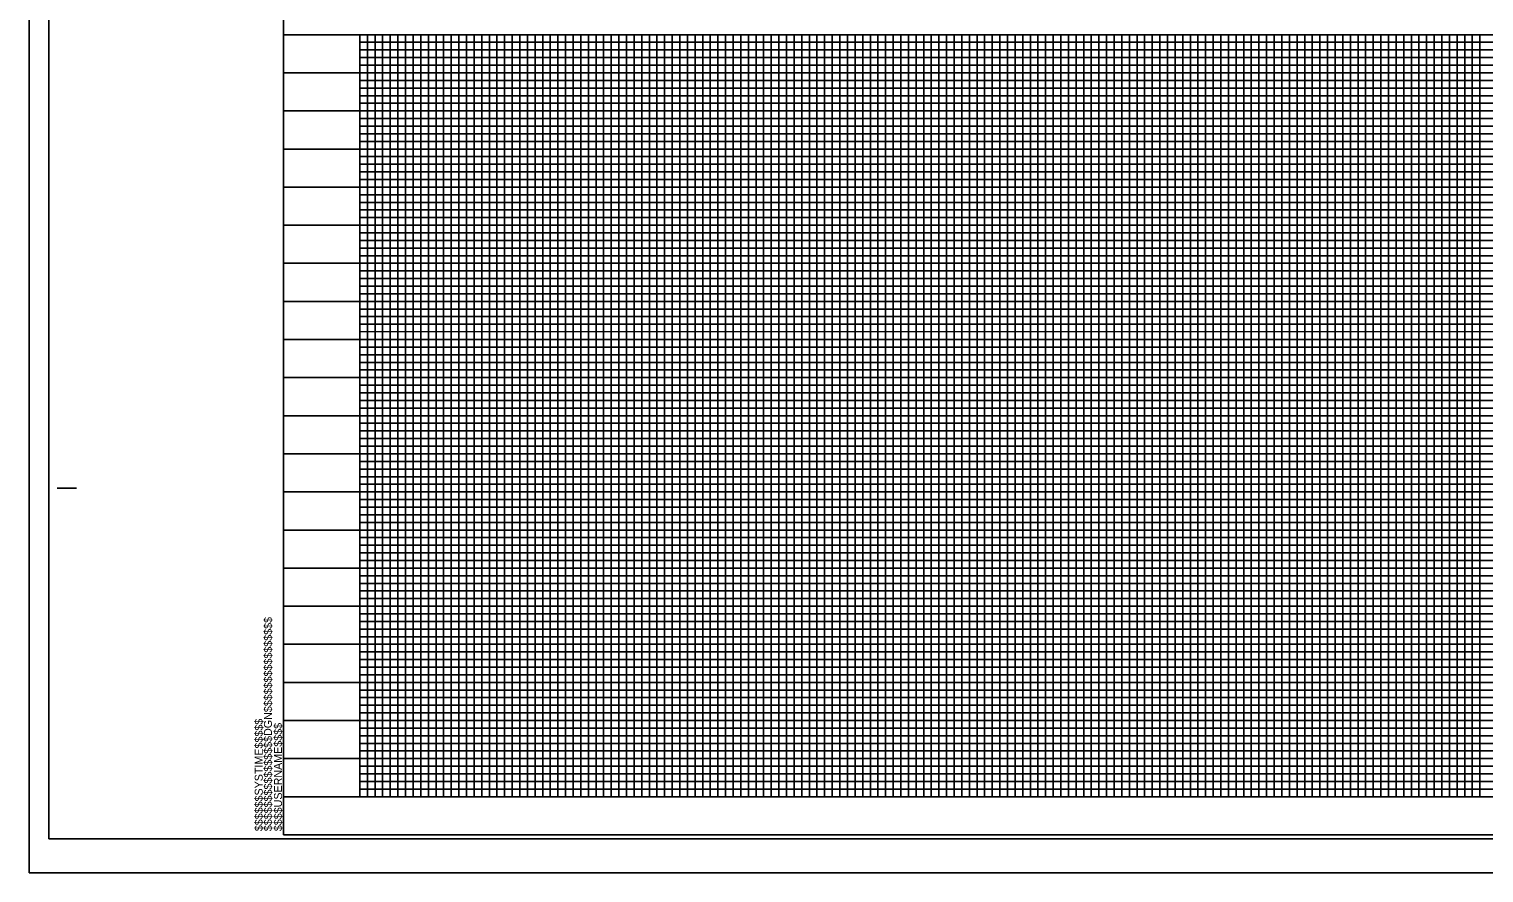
# Model space of a CAD drawing. Extents: x 1754992 to 1757273, y 732111 to 735411.
# Drawn here: x 1755181 to 1756135, y 732111 to 732664 of the extents above; entities that cross this region are included whole.
import ezdxf

# ---------------------------------------------------------------- set-up
doc = ezdxf.new("R2010")
doc.units = 0
for name, color, linetype in [('Scratch_Level_3', 7, 'Continuous'), ('Sheet Cutting Line CELL', 7, 'Continuous'), ('Sheet DOT Grid CELL', 7, 'Continuous'), ('Sheet Plot Border Inside CELL', 7, 'Continuous'), ('Sheet Plot Border Outside CELL', 7, 'Continuous'), ('Sheet Profile CELL', 7, 'Continuous'), ('Sheet Profile Grid Major CELL', 7, 'Continuous'), ('Sheet Profile Grid Middle CELL', 7, 'Continuous'), ('Sheet Profile Grid Minor CELL', 7, 'Continuous')]:
    doc.layers.add(name, color=color, linetype=linetype)

msp = doc.modelspace()

# ---------------------------------------------------------------- linework, layer by layer
at = {"layer": 'Scratch_Level_3'}
msp.add_lwpolyline([(1755397.67, 732660.78), (1756797.67, 732660.78), (1756797.67, 732160.78), (1755397.67, 732160.78)], close=True, dxfattribs=at)
at = {"layer": 'Sheet Cutting Line CELL'}
for p, q in [((1755180.67, 733210.78), (1755180.67, 732110.78)), ((1755180.67, 732110.78), (1756864.67, 732110.78))]:
    msp.add_line(p, q, dxfattribs=at)
at = {"layer": 'Sheet DOT Grid CELL'}
for p, q in [((1755347.67, 732660.78), (1756847.56, 732660.78)), ((1755397.67, 732660.78), (1755397.67, 732160.78)), ((1755447.67, 732660.78), (1755447.67, 732160.78)), ((1755497.67, 732660.78), (1755497.67, 732160.78)), ((1755547.67, 732660.78), (1755547.67, 732160.78)), ((1755597.67, 732660.78), (1755597.67, 732160.78)), ((1755647.67, 732660.78), (1755647.67, 732160.78)), ((1755697.67, 732660.78), (1755697.67, 732160.78)), ((1755747.67, 732660.78), (1755747.67, 732160.78)), ((1755797.67, 732660.78), (1755797.67, 732160.78)), ((1755847.67, 732660.78), (1755847.67, 732160.78)), ((1755897.67, 732660.78), (1755897.67, 732160.78)), ((1755947.67, 732660.78), (1755947.67, 732160.78)), ((1755997.67, 732660.78), (1755997.67, 732160.78)), ((1756047.67, 732660.78), (1756047.67, 732160.78)), ((1756097.67, 732660.78), (1756097.67, 732160.78)), ((1755347.67, 732610.78), (1756847.56, 732610.78)), ((1755347.67, 732560.78), (1756847.56, 732560.78)), ((1755347.67, 732510.78), (1756847.56, 732510.78)), ((1755347.67, 732460.78), (1756847.56, 732460.78)), ((1755347.67, 732410.78), (1756847.56, 732410.78)), ((1755347.67, 732360.78), (1756847.56, 732360.78)), ((1755347.67, 732310.78), (1756847.56, 732310.78)), ((1755347.67, 732260.78), (1756847.56, 732260.78)), ((1755347.67, 732210.78), (1756847.56, 732210.78))]:
    msp.add_line(p, q, dxfattribs=at)
at = {"layer": 'Sheet Plot Border Inside CELL'}
msp.add_lwpolyline([(1755193.67, 732133.23), (1756860.17, 732133.23), (1756860.17, 733188.33), (1755193.67, 733188.33)], close=True, dxfattribs=at)
at = {"layer": 'Sheet Plot Border Outside CELL'}
msp.add_lwpolyline([(1755180.67, 732110.78), (1756864.67, 732110.78), (1756864.67, 733210.78), (1755180.67, 733210.78)], close=True, dxfattribs=at)
at = {"layer": 'Sheet Profile CELL'}
for p, q in [((1755347.67, 732660.78), (1756847.67, 732660.78)), ((1755199.17, 732363.28), (1755211.67, 732363.28)), ((1756847.67, 732160.78), (1755347.67, 732160.78)), ((1755347.67, 732135.78), (1756847.67, 732135.78)), ((1755347.67, 732135.78), (1755347.67, 732135.78)), ((1755347.67, 732135.78), (1755347.67, 732135.78)), ((1755347.67, 732135.78), (1755347.67, 732135.78)), ((1755347.67, 732135.78), (1755347.67, 732135.78)), ((1755347.67, 732135.78), (1755347.67, 732135.78)), ((1755347.67, 732135.78), (1755347.67, 732135.78)), ((1755347.67, 732135.78), (1755347.67, 732135.78))]:
    msp.add_line(p, q, dxfattribs=at)
msp.add_lwpolyline([(1756847.67, 733185.78), (1755347.67, 733185.78), (1755347.67, 732135.78), (1756847.67, 732135.78)], close=True, dxfattribs=at)
msp.add_lwpolyline([(1755385.17, 732135.78), (1755385.17, 732135.78)], dxfattribs=at)
at = {"layer": 'Sheet Profile Grid Major CELL'}
for p, q in [((1755847.67, 732660.78), (1755897.67, 732660.78)), ((1755947.67, 732660.78), (1755997.67, 732660.78)), ((1756047.67, 732660.78), (1756097.67, 732660.78)), ((1755347.67, 732160.78), (1755347.67, 732160.78))]:
    msp.add_line(p, q, dxfattribs=at)
for points in [[(1755397.67, 732660.78), (1755397.67, 732160.78), (1755447.67, 732160.78), (1755447.67, 732660.78), (1755497.67, 732660.78), (1755497.67, 732160.78), (1755547.67, 732160.78), (1755547.67, 732660.78), (1755597.67, 732660.78), (1755597.67, 732160.78), (1755647.67, 732160.78), (1755647.67, 732660.78), (1755697.67, 732660.78), (1755697.67, 732160.78), (1755747.67, 732160.78), (1755747.67, 732660.78), (1755797.67, 732660.78), (1755797.67, 732160.78), (1755847.67, 732160.78), (1755847.67, 732660.78), (1755897.67, 732660.78), (1755897.67, 732160.78), (1755947.67, 732160.78), (1755947.67, 732660.78), (1755997.67, 732660.78), (1755997.67, 732160.78), (1756047.67, 732160.78), (1756047.67, 732660.78), (1756097.67, 732660.78), (1756097.67, 732160.78), (1756147.67, 732160.78)], [(1756847.67, 732610.78), (1755347.67, 732610.78)], [(1756847.67, 732560.78), (1755347.67, 732560.78), (1755347.67, 732510.78), (1756847.67, 732510.78)], [(1756847.67, 732460.78), (1755347.67, 732460.78), (1755347.67, 732410.78), (1756847.67, 732410.78)], [(1756847.67, 732360.78), (1755347.67, 732360.78), (1755347.67, 732310.78), (1756847.67, 732310.78)], [(1756847.67, 732260.78), (1755347.67, 732260.78), (1755347.67, 732260.78), (1755347.67, 732210.78), (1756847.67, 732210.78)], [(1756847.67, 732160.78), (1755347.67, 732160.78)]]:
    msp.add_lwpolyline(points, dxfattribs=at)
at = {"layer": 'Sheet Profile Grid Middle CELL'}
for points in [[(1755372.67, 732660.78), (1755422.67, 732660.78), (1755422.67, 732160.78), (1755472.67, 732160.78), (1755472.67, 732660.78), (1755522.67, 732660.78), (1755522.67, 732160.78), (1755572.67, 732160.78), (1755572.67, 732660.78), (1755622.67, 732660.78), (1755622.67, 732160.78), (1755672.67, 732160.78), (1755672.67, 732660.78), (1755722.67, 732660.78), (1755722.67, 732160.78), (1755772.67, 732160.78), (1755772.67, 732660.78), (1755822.67, 732660.78), (1755822.67, 732160.78), (1755872.67, 732160.78), (1755872.67, 732660.78), (1755922.67, 732660.78), (1755922.67, 732160.78), (1755972.67, 732160.78), (1755972.67, 732160.78), (1755972.67, 732660.78), (1756022.67, 732660.78), (1756022.67, 732160.78), (1756072.67, 732160.78), (1756072.67, 732660.78), (1756122.67, 732660.78), (1756122.67, 732160.78), (1756172.67, 732160.78)], [(1755347.67, 732635.78), (1756847.67, 732635.78)], [(1756847.67, 732585.78), (1755347.67, 732585.78), (1755347.67, 732535.78), (1756847.67, 732535.78)], [(1756847.67, 732485.78), (1755347.67, 732485.78), (1755347.67, 732435.78), (1756847.67, 732435.78)], [(1756847.67, 732385.78), (1755347.67, 732385.78), (1755347.67, 732335.78), (1756847.67, 732335.78)], [(1756847.67, 732285.78), (1755347.67, 732285.78), (1755347.67, 732235.78), (1756847.67, 732235.78)], [(1756847.67, 732185.78), (1755347.67, 732185.78)]]:
    msp.add_lwpolyline(points, dxfattribs=at)
at = {"layer": 'Sheet Profile Grid Minor CELL'}
for p, q in [((1755397.67, 732655.78), (1756797.67, 732655.78)), ((1756797.67, 732650.78), (1755397.67, 732650.78)), ((1755397.67, 732645.78), (1756797.67, 732645.78)), ((1756797.67, 732640.78), (1755397.67, 732640.78)), ((1755397.67, 732630.78), (1756797.67, 732630.78)), ((1756797.67, 732625.78), (1755397.67, 732625.78)), ((1755397.67, 732620.78), (1756797.67, 732620.78)), ((1756797.67, 732615.78), (1755397.67, 732615.78)), ((1755397.67, 732605.78), (1756797.67, 732605.78)), ((1756797.67, 732600.78), (1755397.67, 732600.78)), ((1755397.67, 732595.78), (1756797.67, 732595.78)), ((1756797.67, 732590.78), (1755397.67, 732590.78)), ((1755397.67, 732580.78), (1756797.67, 732580.78)), ((1756797.67, 732575.78), (1755397.67, 732575.78)), ((1755397.67, 732570.78), (1756797.67, 732570.78)), ((1756797.67, 732565.78), (1755397.67, 732565.78)), ((1755397.67, 732555.78), (1756797.67, 732555.78)), ((1756797.67, 732550.78), (1755397.67, 732550.78)), ((1755397.67, 732545.78), (1756797.67, 732545.78)), ((1756797.67, 732540.78), (1755397.67, 732540.78)), ((1755397.67, 732530.78), (1756797.67, 732530.78)), ((1756797.67, 732525.78), (1755397.67, 732525.78)), ((1755397.67, 732520.78), (1756797.67, 732520.78)), ((1756797.67, 732515.78), (1755397.67, 732515.78)), ((1755397.67, 732505.78), (1756797.67, 732505.78)), ((1756797.67, 732500.78), (1755397.67, 732500.78)), ((1755397.67, 732495.78), (1756797.67, 732495.78)), ((1756797.67, 732490.78), (1755397.67, 732490.78)), ((1755397.67, 732480.78), (1756797.67, 732480.78)), ((1756797.67, 732475.78), (1755397.67, 732475.78)), ((1755397.67, 732470.78), (1756797.67, 732470.78)), ((1756797.67, 732465.78), (1755397.67, 732465.93)), ((1755397.67, 732455.78), (1756797.67, 732455.78)), ((1756797.67, 732450.78), (1755397.67, 732450.78)), ((1755397.67, 732445.78), (1756797.67, 732445.78)), ((1756797.67, 732440.78), (1755397.67, 732440.78)), ((1755397.67, 732430.78), (1756797.67, 732430.78)), ((1756797.67, 732425.78), (1755397.67, 732425.78)), ((1755397.67, 732420.78), (1756797.67, 732420.78)), ((1756797.67, 732415.78), (1755397.67, 732415.78)), ((1755397.67, 732405.78), (1756797.67, 732405.78)), ((1756797.67, 732400.78), (1755397.67, 732400.78)), ((1755397.67, 732395.78), (1756797.67, 732395.78)), ((1756797.67, 732390.78), (1755397.67, 732390.78)), ((1755397.67, 732380.78), (1756797.67, 732380.78)), ((1756797.67, 732375.78), (1755397.67, 732375.78)), ((1755397.67, 732370.78), (1756797.67, 732370.78)), ((1756797.67, 732365.78), (1755397.67, 732365.78)), ((1755397.67, 732355.78), (1756797.67, 732355.78)), ((1756797.67, 732350.78), (1755397.67, 732350.78)), ((1755397.67, 732345.78), (1756797.67, 732345.78)), ((1756797.67, 732340.78), (1755397.67, 732340.78)), ((1755397.67, 732330.78), (1756797.67, 732330.78)), ((1756797.67, 732325.78), (1755397.67, 732325.78)), ((1755397.67, 732320.78), (1756797.67, 732320.78)), ((1756797.67, 732315.78), (1755397.67, 732315.78)), ((1755397.67, 732305.78), (1756797.67, 732305.78)), ((1756797.67, 732300.78), (1755397.67, 732300.78)), ((1755397.67, 732295.78), (1756797.67, 732295.78)), ((1756797.67, 732290.78), (1755397.67, 732290.78)), ((1755397.67, 732280.78), (1756797.67, 732280.78)), ((1756797.67, 732275.78), (1755397.67, 732275.78)), ((1755397.67, 732270.78), (1756797.67, 732270.78)), ((1756797.67, 732265.78), (1755397.67, 732265.78)), ((1755397.67, 732255.78), (1756797.67, 732255.78)), ((1756797.67, 732250.78), (1755397.67, 732250.78)), ((1755397.67, 732245.78), (1756797.67, 732245.78)), ((1756797.67, 732240.78), (1755397.67, 732240.78)), ((1755397.67, 732230.78), (1756797.67, 732230.78)), ((1756797.67, 732225.78), (1755397.67, 732225.78)), ((1755397.67, 732220.78), (1756797.67, 732220.78)), ((1756797.67, 732215.78), (1755397.67, 732215.78)), ((1755397.67, 732205.78), (1756797.67, 732205.78)), ((1756797.67, 732200.78), (1755397.67, 732200.78)), ((1755397.67, 732195.78), (1756797.67, 732195.78)), ((1756797.67, 732190.78), (1755397.67, 732190.78)), ((1755397.67, 732180.78), (1756797.67, 732180.78)), ((1756797.67, 732175.78), (1755397.67, 732175.78)), ((1755397.67, 732170.78), (1756797.67, 732170.78)), ((1755397.67, 732165.78), (1756797.67, 732165.78))]:
    msp.add_line(p, q, dxfattribs=at)
for points in [[(1755397.67, 732660.78), (1755402.67, 732660.78), (1755402.67, 732160.78), (1755407.67, 732160.78), (1755407.67, 732660.78), (1755412.67, 732660.78), (1755412.67, 732160.78), (1755417.67, 732160.78), (1755417.67, 732660.78), (1755427.67, 732660.78), (1755427.67, 732160.78), (1755432.67, 732160.78), (1755432.67, 732660.78), (1755437.67, 732660.78), (1755437.67, 732160.78), (1755442.67, 732160.78), (1755452.67, 732160.78), (1755457.67, 732160.78), (1755457.67, 732660.78), (1755462.67, 732660.78), (1755462.67, 732160.78), (1755467.67, 732160.78), (1755467.67, 732660.78), (1755477.67, 732660.78), (1755477.67, 732160.78), (1755482.67, 732160.78), (1755482.67, 732660.78), (1755487.67, 732660.78), (1755487.67, 732160.78), (1755492.67, 732160.78), (1755492.67, 732660.78), (1755502.67, 732660.78), (1755502.67, 732160.78), (1755507.67, 732160.78), (1755507.67, 732660.78), (1755512.67, 732660.78), (1755512.67, 732160.78), (1755517.67, 732160.78), (1755517.67, 732660.78), (1755527.67, 732660.78), (1755527.67, 732160.78), (1755532.67, 732160.78), (1755532.67, 732660.78), (1755537.67, 732660.78), (1755537.67, 732160.78), (1755542.67, 732160.78), (1755542.67, 732660.78), (1755552.67, 732660.78), (1755552.67, 732160.78), (1755557.67, 732160.78), (1755557.67, 732660.78), (1755562.67, 732660.78), (1755562.67, 732160.78), (1755567.67, 732160.78), (1755567.67, 732660.78), (1755577.67, 732660.78), (1755577.67, 732160.78), (1755582.67, 732160.78), (1755582.67, 732660.78), (1755587.67, 732660.78), (1755587.67, 732160.78), (1755592.67, 732160.78), (1755592.67, 732660.78), (1755602.67, 732660.78), (1755602.67, 732160.78), (1755607.67, 732160.78), (1755607.67, 732660.78), (1755612.67, 732660.78), (1755612.67, 732160.78)], [(1755442.67, 732160.78), (1755442.67, 732660.78), (1755452.67, 732660.78), (1755452.67, 732160.78)], [(1755612.67, 732160.78), (1755617.67, 732160.78), (1755617.67, 732660.78), (1755627.67, 732660.78), (1755627.67, 732160.78), (1755632.67, 732160.78), (1755632.67, 732660.78), (1755637.67, 732660.78), (1755637.67, 732160.78), (1755642.67, 732160.78), (1755642.67, 732660.78), (1755652.67, 732660.78), (1755652.67, 732160.78), (1755657.67, 732160.78), (1755657.67, 732660.78), (1755662.67, 732660.78), (1755662.67, 732160.78), (1755667.67, 732160.78), (1755667.67, 732660.78), (1755677.67, 732660.78), (1755677.67, 732160.78), (1755682.67, 732160.78), (1755682.67, 732660.78), (1755687.67, 732660.78), (1755687.67, 732160.78), (1755692.67, 732160.78), (1755692.67, 732660.78), (1755702.67, 732660.78), (1755702.67, 732160.78), (1755707.67, 732160.78), (1755707.67, 732660.78), (1755712.67, 732660.78), (1755712.67, 732160.78), (1755717.67, 732160.78), (1755717.67, 732660.78), (1755727.67, 732660.78), (1755727.67, 732160.78), (1755732.67, 732160.78), (1755732.67, 732660.78), (1755737.67, 732660.78), (1755737.67, 732160.78), (1755742.67, 732160.78), (1755742.67, 732660.78), (1755752.67, 732660.78), (1755752.67, 732160.78), (1755757.67, 732160.78), (1755757.67, 732660.78), (1755762.67, 732660.78), (1755762.67, 732160.78), (1755767.67, 732160.78), (1755767.67, 732660.78), (1755777.67, 732660.78), (1755777.67, 732160.78), (1755782.67, 732160.78), (1755782.67, 732660.78), (1755787.67, 732660.78), (1755787.67, 732160.78), (1755792.67, 732160.78), (1755792.67, 732660.78), (1755802.67, 732660.78), (1755802.67, 732160.78), (1755807.67, 732160.78), (1755807.67, 732660.78), (1755812.67, 732660.78), (1755812.67, 732160.78), (1755817.67, 732160.78), (1755817.67, 732660.78), (1755827.67, 732660.78), (1755827.67, 732160.78), (1755832.67, 732160.78), (1755832.67, 732660.78), (1755837.67, 732660.78), (1755837.67, 732160.78), (1755842.67, 732160.78), (1755842.67, 732660.78), (1755852.67, 732660.78), (1755852.67, 732160.78), (1755857.67, 732160.78), (1755857.67, 732660.78), (1755862.67, 732660.78), (1755862.67, 732160.78), (1755867.67, 732160.78), (1755867.67, 732660.78), (1755877.67, 732660.78), (1755877.67, 732160.78), (1755882.67, 732160.78), (1755882.67, 732660.78), (1755887.67, 732660.78), (1755887.67, 732160.78), (1755892.67, 732160.78), (1755892.67, 732660.78), (1755902.67, 732660.78), (1755902.67, 732160.78), (1755907.67, 732160.78), (1755907.67, 732660.78), (1755912.67, 732660.78), (1755912.67, 732160.78), (1755917.67, 732160.78), (1755917.67, 732660.78), (1755927.67, 732660.78)], [(1755927.67, 732660.78), (1755927.67, 732160.78), (1755932.67, 732160.78), (1755932.67, 732660.78), (1755937.67, 732660.78), (1755937.67, 732160.78), (1755942.67, 732160.78), (1755942.67, 732660.78), (1755952.67, 732660.78), (1755952.67, 732160.78), (1755957.67, 732160.78), (1755957.67, 732660.78), (1755962.67, 732660.78), (1755962.67, 732160.78), (1755967.67, 732160.78), (1755967.67, 732660.78), (1755977.67, 732660.78), (1755977.67, 732160.78), (1755982.67, 732160.78), (1755982.67, 732660.78), (1755987.67, 732660.78), (1755987.67, 732160.78), (1755992.67, 732160.78), (1755992.67, 732660.78), (1756002.67, 732660.78), (1756002.67, 732160.78), (1756007.67, 732160.78), (1756007.67, 732660.78), (1756012.67, 732660.78), (1756012.67, 732160.78), (1756017.67, 732160.78), (1756017.67, 732660.78), (1756027.67, 732660.78), (1756027.67, 732160.78), (1756032.67, 732160.78), (1756032.67, 732660.78), (1756037.67, 732660.78), (1756037.67, 732160.78), (1756042.67, 732160.78), (1756042.67, 732660.78), (1756052.67, 732660.78), (1756052.67, 732160.78), (1756052.67, 732160.78), (1756057.67, 732160.78), (1756057.67, 732660.78), (1756062.67, 732660.78), (1756062.67, 732160.78), (1756067.67, 732160.78), (1756067.67, 732660.78), (1756077.67, 732660.78), (1756077.67, 732160.78), (1756082.67, 732160.78), (1756082.67, 732660.78), (1756087.67, 732660.78), (1756087.67, 732160.78), (1756092.67, 732160.78), (1756092.67, 732660.78), (1756102.67, 732660.78), (1756102.67, 732160.78), (1756107.67, 732160.78), (1756107.67, 732660.78), (1756112.67, 732660.78), (1756112.67, 732160.78), (1756117.67, 732160.78), (1756117.67, 732660.78), (1756127.67, 732660.78), (1756127.67, 732160.78), (1756132.67, 732160.78), (1756132.67, 732660.78), (1756137.67, 732660.78)]]:
    msp.add_lwpolyline(points, dxfattribs=at)

# ---------------------------------------------------------------- texts
at = {"layer": 'Sheet Profile CELL'}
for s, p in [('$$$$$$$$$$$$$$$$DGN$$$$$$$$$$$$$$$$', (1755340.03, 732138.16)), ('$$$$$$SYSTIME$$$$$', (1755333.98, 732138.16)), ('$$$$USERNAME$$$$', (1755346.61, 732138.17))]:
    msp.add_text(s, height=5.25, rotation=90, dxfattribs=at).set_placement(p)

doc.saveas('drawing.dxf')
